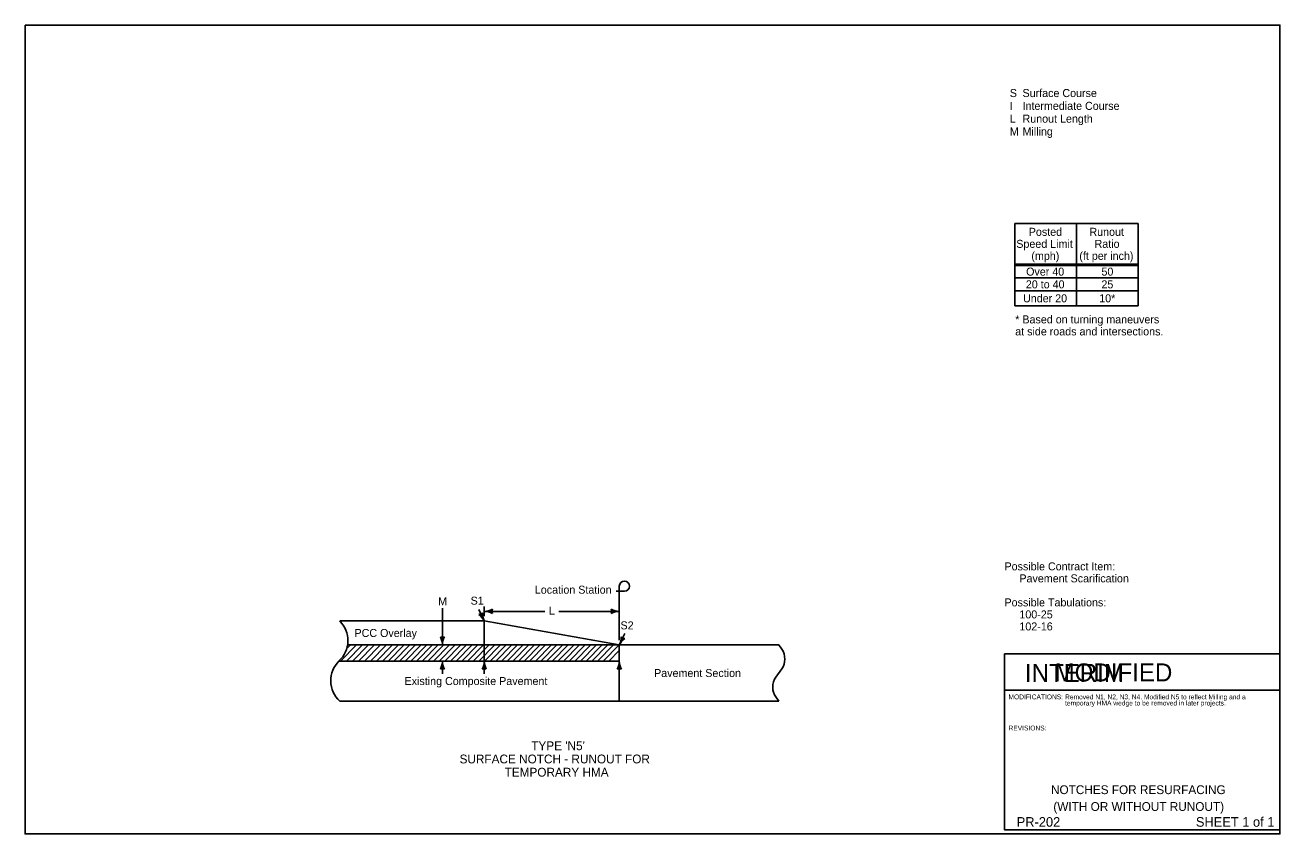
# Model space of a CAD drawing. Extents: x 10133 to 81668, y 7924 to 12178.
# Drawn here: x 10133 to 13268, y 7924 to 9944 of the extents above; entities that cross this region are included whole.
import ezdxf

# ---------------------------------------------------------------- set-up
doc = ezdxf.new("R2010")
doc.units = 0
for name, color, linetype in [('dsnStdBlock', 7, 'Continuous'), ('dsnStdBlockNotModified', 7, 'Continuous'), ('dsnStdBorder', 7, 'Continuous'), ('dsnStdLabel', 7, 'Continuous'), ('dsnStdLineWork', 7, 'Continuous'), ('dsnStdShading', 7, 'Continuous'), ('Level 3', 7, 'Continuous'), ('SheetBorder', 7, 'Continuous')]:
    doc.layers.add(name, color=color, linetype=linetype)

msp = doc.modelspace()

# ---------------------------------------------------------------- linework, layer by layer
at = {"layer": 'dsnStdBlock'}
for p, q in [((12605.4, 9448.5), (12605.4, 9243)), ((12605.4, 9448.5), (12913.4, 9448.5)), ((12759.7, 9448.5), (12759.7, 9243)), ((12913.4, 9448.5), (12913.4, 9243)), ((12605.4, 9346.8), (12913.4, 9346.8)), ((12605.4, 9343.8), (12913.4, 9343.8)), ((12605.4, 9312.7), (12913.4, 9312.7)), ((12605.4, 9280.3), (12913.4, 9280.3)), ((12605.4, 9243), (12913.4, 9243)), ((11629.8, 8530), (11609.5, 8530)), ((11617.1, 8522.4), (11617.1, 8542.7)), ((11617.1, 8522.4), (11617.1, 8407.8)), ((11175.3, 8487.8), (11175.3, 8395.8)), ((11265.8, 8484.7), (11279.6, 8455.8)), ((11279.6, 8491.8), (11279.6, 8467.8)), ((11279.6, 8479.8), (11430.9, 8479.8)), ((11465.9, 8479.8), (11617.1, 8479.8)), ((10918.5, 8455.8), (11279.6, 8455.8)), ((11617.1, 8395.8), (11279.6, 8455.8)), ((11279.6, 8355.8), (11279.6, 8455.8)), ((11175.4, 8414.1), (11177.2, 8415.8)), ((11631.3, 8424.5), (11617.1, 8395.8)), ((10920.5, 8355.8), (10960.4, 8395.8)), ((10935.5, 8355.8), (10975.4, 8395.8)), ((10935.6, 8385.9), (10945.4, 8395.8)), ((10938.1, 8395.8), (11279.6, 8395.8)), ((10950.5, 8355.8), (10990.4, 8395.8)), ((10965.5, 8355.8), (11005.4, 8395.8)), ((10980.5, 8355.8), (11020.4, 8395.8)), ((10995.5, 8355.8), (11035.4, 8395.8)), ((11010.5, 8355.8), (11050.4, 8395.8)), ((11025.5, 8355.8), (11065.4, 8395.8)), ((11039.6, 8355.8), (11079.6, 8395.8)), ((11053.7, 8355.8), (11093.7, 8395.8)), ((11067.9, 8355.8), (11107.9, 8395.8)), ((11082, 8355.8), (11122, 8395.8)), ((11096.2, 8355.8), (11136.2, 8395.8)), ((11110.3, 8355.8), (11150.3, 8395.8)), ((11124.4, 8355.8), (11164.4, 8395.8)), ((11138.6, 8355.8), (11178.6, 8395.8)), ((11152.7, 8355.8), (11192.7, 8395.8)), ((11166.9, 8355.8), (11206.9, 8395.8)), ((11181, 8355.8), (11221, 8395.8)), ((11195.2, 8355.8), (11235.2, 8395.8)), ((11209.3, 8355.8), (11249.3, 8395.8)), ((11223.4, 8355.8), (11263.4, 8395.8)), ((11237.6, 8355.8), (11277.6, 8395.8)), ((11251.7, 8355.8), (11291.7, 8395.8)), ((11265.9, 8355.8), (11305.9, 8395.8)), ((11279.6, 8395.8), (11617.1, 8395.8)), ((11280, 8355.8), (11320, 8395.8)), ((11294.2, 8355.8), (11334.2, 8395.8)), ((11308.3, 8355.8), (11348.3, 8395.8)), ((11322.4, 8355.8), (11362.4, 8395.8)), ((11336.6, 8355.8), (11376.6, 8395.8)), ((11350.7, 8355.8), (11390.7, 8395.8)), ((11364.9, 8355.8), (11404.9, 8395.8)), ((11379, 8355.8), (11419, 8395.8)), ((11393.1, 8355.8), (11433.1, 8395.8)), ((11407.3, 8355.8), (11447.3, 8395.8)), ((11421.4, 8355.8), (11461.4, 8395.8)), ((11435.6, 8355.8), (11475.6, 8395.8)), ((11449.7, 8355.8), (11489.7, 8395.8)), ((11463.9, 8355.8), (11503.9, 8395.8)), ((11478, 8355.8), (11518, 8395.8)), ((11492.1, 8355.8), (11532.1, 8395.8)), ((11506.3, 8355.8), (11546.3, 8395.8)), ((11520.4, 8355.8), (11560.4, 8395.8)), ((11534.6, 8355.8), (11574.6, 8395.8)), ((11548.7, 8355.8), (11588.7, 8395.8)), ((11562.9, 8355.8), (11602.9, 8395.8)), ((11577, 8355.8), (11617, 8395.8)), ((11591.1, 8355.8), (11617.1, 8381.8)), ((11617.1, 8395.8), (11617.1, 8255.8)), ((11617.1, 8395.8), (12015.6, 8395.8)), ((12015.6, 8395.8), (12023.1, 8385.6)), ((10916.6, 8355.8), (11617.1, 8355.8)), ((11175.3, 8355.8), (11175.3, 8323.8)), ((11279.6, 8355.8), (11279.6, 8323.8)), ((11617.1, 8355.8), (11617.1, 8323.8)), ((12023.1, 8336.1), (12008.1, 8315.6)), ((10918.5, 8255.8), (12015.6, 8255.8)), ((12008.1, 8266.1), (12015.6, 8255.8))]:
    msp.add_line(p, q, dxfattribs=at)
for centre, radius, start, end in [((11629.8, 8542.7), 12.7, 270, 180), ((11264, 8488.5), 16.7, 277.8386, 313.3053), ((11240.6, 8437.2), 43.2, 25.572, 53.6444), ((11318.6, 8474.5), 43.2, 177.4995, 205.572), ((11279.6, 8523), 43.2, 270, 298.0725), ((11279.6, 8436.6), 43.2, 61.9275, 90), ((11315.8, 8479.8), 16.7, 162.2666, 197.7334), ((11580.9, 8479.8), 16.7, 342.2666, 17.7333), ((11617.1, 8523), 43.2, 241.9275, 270), ((11617.1, 8436.6), 43.2, 90, 118.0725), ((10870, 8406.7), 69, 312.5067, 45.3792), ((11175.3, 8432), 16.7, 252.2666, 287.7333), ((11132.1, 8395.8), 43.2, 360, 28.0725), ((11218.4, 8395.8), 43.2, 151.9275, 180), ((11578.4, 8415), 43.2, 333.5865, 1.659), ((11655.8, 8376.6), 43.2, 125.514, 153.5865), ((11633.2, 8428.2), 16.7, 225.8531, 261.3198), ((10965.1, 8306.7), 69, 134.6239, 227.4897), ((11132.1, 8355.8), 43.2, 331.9275, 360), ((11218.4, 8355.8), 43.2, 180, 208.0725), ((11236.4, 8355.8), 43.2, 331.9275, 360), ((11322.8, 8355.8), 43.2, 180, 208.0725), ((11573.9, 8355.8), 43.2, 331.9275, 360), ((11660.3, 8355.8), 43.2, 180, 208.0725), ((11175.3, 8319.6), 16.7, 72.2666, 107.7334), ((11279.6, 8319.6), 16.7, 72.2666, 107.7334), ((11617.1, 8319.6), 16.7, 72.2666, 107.7334)]:
    msp.add_arc(centre, radius, start, end, dxfattribs=at)
for centre, major_axis in [((12005, 8360.8), (0, -35)), ((12026.2, 8290.8), (0, 35))]:
    msp.add_ellipse(centre, major_axis=major_axis, ratio=0.732627, start_param=0.785398, end_param=2.356194, dxfattribs=at)
at = {"layer": 'dsnStdBlockNotModified'}
msp.add_lwpolyline([(10918.5, 8455.8), (11279.6, 8455.8), (11279.6, 8355.8), (10916.6, 8355.8)], dxfattribs=at)
msp.add_lwpolyline([(11279.6, 8355.8), (11279.6, 8455.8), (11617.1, 8395.8), (11617.1, 8355.8)], close=True, dxfattribs=at)
msp.add_arc((10870, 8406.7), 69, 312.5067, 45.3792, dxfattribs=at)
at = {"layer": 'Level 3'}
msp.add_line((12579.5, 8282.7), (13267.5, 8282.7), dxfattribs=at)
msp.add_lwpolyline([(12579.5, 8374), (13267.5, 8374), (13267.5, 7934), (12579.5, 7934)], close=True, dxfattribs=at)
at = {"layer": 'SheetBorder'}
msp.add_lwpolyline([(10132.5, 9944), (13267.5, 9944), (13267.5, 7924), (10132.5, 7924)], close=True, dxfattribs=at)

# ---------------------------------------------------------------- texts
at = {"layer": 'dsnStdBlock'}
for s, p in [('Possible Contract Item:', (12579.5, 8582.2)), ('     Pavement Scarification', (12579.5, 8552.2)), ('Possible Tabulations:', (12579.5, 8492.2)), ('     100-25', (12579.5, 8462.2)), ('PCC Overlay', (10955.5, 8415.8)), ('     102-16', (12579.5, 8432.2)), ('Existing Composite Pavement', (11080.6, 8295.8)), ('Pavement Section', (11704, 8315.8))]:
    msp.add_text(s, height=20, dxfattribs=at).set_placement(p)
at = {"layer": 'dsnStdBorder'}
for s, height, p in [('S', 20, (12592.8, 9764.3)), ('Surface Course', 20, (12624.5, 9764.3)), ('I', 20, (12592.5, 9732.3)), ('Intermediate Course', 20, (12624.5, 9732.3)), ('L', 20, (12592.5, 9700.3)), ('Runout Length', 20, (12624.5, 9700.3)), ('M', 20, (12592.7, 9668.3)), ('Milling', 20, (12624.5, 9668.3)), ('Posted', 20, (12640.1, 9417.7)), ('Runout', 20, (12791.6, 9417.7)), ('Speed Limit', 20, (12608.9, 9387.7)), ('Ratio', 20, (12804.5, 9387.7)), ('(mph)', 20, (12646.6, 9357.7)), ('(ft per inch)', 20, (12766.4, 9357.7)), ('Over 40', 20, (12633.5, 9318.3)), ('50', 20, (12821.7, 9318.3)), ('20 to 40', 20, (12632.8, 9286.5)), ('25', 20, (12821.6, 9286.5)), ('Under 20', 20, (12625.8, 9251.7)), ('10*', 20, (12816.1, 9251.7)), ('* Based on turning maneuvers ', 20, (12606.3, 9199)), ('at side roads and intersections.', 20, (12606.3, 9169)), ('Location Station', 20, (11406, 8523.9)), ('M', 20, (11164.5, 8494.9)), ('S1', 20, (11245.6, 8496.5)), ('L', 20, (11441.3, 8471.6)), ('S2', 20, (11620.1, 8434.8)), ("TYPE 'N5'", 22, (11397.1, 8133.1)), ('SURFACE NOTCH - RUNOUT FOR', 22, (11218, 8100.1)), ('TEMPORARY HMA', 22, (11330.5, 8067.1))]:
    msp.add_text(s, height=height, dxfattribs=at).set_placement(p)
at = {"layer": 'dsnStdLabel'}
msp.add_text('REVISIONS:', height=12, dxfattribs=at).set_placement((12589.5, 8182.4))
at = {"layer": 'dsnStdLineWork'}
for s, height, p in [('MODIFIED', 45, (12704.6, 8304.8)), ('MODIFICATIONS:', 12, (12589.5, 8260.2))]:
    msp.add_text(s, height=height, dxfattribs=at).set_placement(p)
at = {"layer": 'dsnStdShading'}
msp.add_text('INTERIM', height=45, dxfattribs=at).set_placement((12630.5, 8303.7))
at = {"layer": 'Level 3'}
for s, height, p in [('temporary HMA wedge to be removed in later projects.', 12, (12730.8, 8244.7)), ('Removed N1, N2, N3, N4. Modified N5 to reflect Milling and a ', 12, (12730.8, 8260.2)), ('NOTCHES FOR RESURFACING', 22, (12695.6, 8023.4)), ('(WITH OR WITHOUT RUNOUT)', 22, (12701.5, 7981.4)), ('PR-202', 24, (12609.9, 7941.9)), ('SHEET 1 of 1', 24, (13057.6, 7941.9))]:
    msp.add_text(s, height=height, dxfattribs=at).set_placement(p)

doc.saveas('drawing.dxf')
